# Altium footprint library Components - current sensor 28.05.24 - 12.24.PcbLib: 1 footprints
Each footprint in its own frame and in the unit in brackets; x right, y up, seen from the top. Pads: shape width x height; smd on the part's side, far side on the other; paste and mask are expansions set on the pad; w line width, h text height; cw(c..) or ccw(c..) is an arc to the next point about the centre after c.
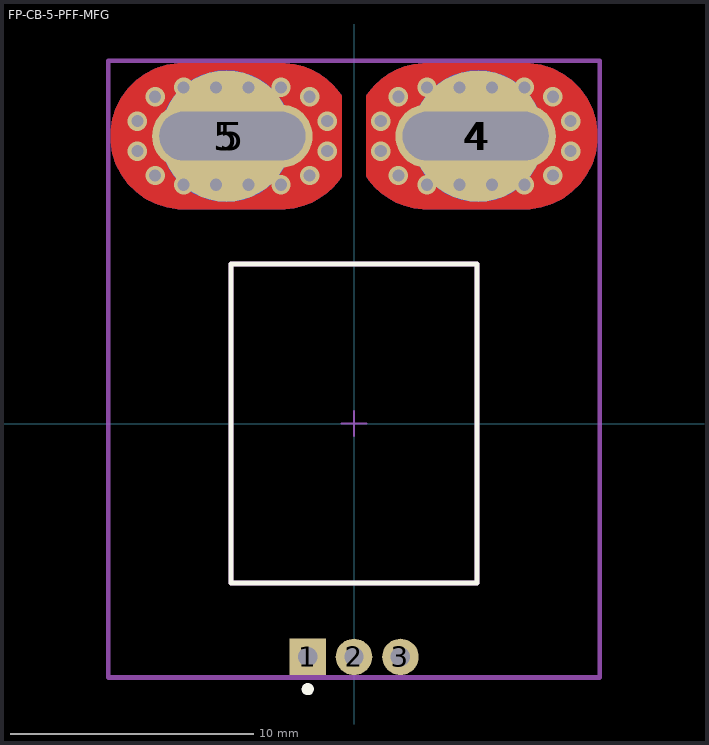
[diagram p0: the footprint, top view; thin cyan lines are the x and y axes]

## FP-CB-5-PFF-MFG [mm]
pads (9):
  rect 1.5x1.5 hole 0.8 paste-2539.97 mask+0: 1(-1.91,-9.59)
  round 1.5 hole 0.8 paste-2539.97 mask+0: 2(0,-9.59) 3(1.91,-9.59)
  rrect100% 6.6x2.6 hole 2 slot 6 at 0 deg paste-2539.97 mask+0: 4(5,11.809) 5(-5,11.809)
  round 5.4 smd paste-1000 mask+0: 4(5.099,11.809) 5(-5.25,11.809)
  round 5.4 smd far side paste-1000 mask+0: 4(5.099,11.809) 5(-5.25,11.809)
via 1.824,10.192 diameter 0.8 hole 0.5
via -1.824,10.192 diameter 0.8 hole 0.5
via 1.098,11.191 diameter 0.8 hole 0.5
via -1.098,11.191 diameter 0.8 hole 0.5
via 1.098,12.428 diameter 0.8 hole 0.5
via -1.098,12.428 diameter 0.8 hole 0.5
via 1.824,13.427 diameter 0.8 hole 0.5
via -1.824,13.427 diameter 0.8 hole 0.5
via 8.176,10.192 diameter 0.8 hole 0.5
via -8.176,10.192 diameter 0.8 hole 0.5
via 8.902,11.191 diameter 0.8 hole 0.5
via -8.902,11.191 diameter 0.8 hole 0.5
via 8.902,12.428 diameter 0.8 hole 0.5
via -8.902,12.428 diameter 0.8 hole 0.5
via 8.176,13.427 diameter 0.8 hole 0.5
via -8.176,13.427 diameter 0.8 hole 0.5
via 7,9.81 diameter 0.8 hole 0.5
via 5.667,9.81 diameter 0.8 hole 0.5
via 4.333,9.81 diameter 0.8 hole 0.5
via 3,9.81 diameter 0.8 hole 0.5
via 7,13.809 diameter 0.8 hole 0.5
via 5.667,13.809 diameter 0.8 hole 0.5
via 4.333,13.809 diameter 0.8 hole 0.5
via 3,13.809 diameter 0.8 hole 0.5
via -3,9.81 diameter 0.8 hole 0.5
via -4.333,9.81 diameter 0.8 hole 0.5
via -5.667,9.81 diameter 0.8 hole 0.5
via -7,9.81 diameter 0.8 hole 0.5
via -3,13.809 diameter 0.8 hole 0.5
via -4.333,13.809 diameter 0.8 hole 0.5
via -5.667,13.809 diameter 0.8 hole 0.5
via -7,13.809 diameter 0.8 hole 0.5
Top Layer:
  region: 0.5,13.468 0.602,13.622 0.843,13.903 1.116,14.152 1.418,14.365 1.744,14.54 2.089,14.674 2.448,14.764 2.815,14.809 3,14.809 7,14.809 7.236,14.809 7.703,14.736 8.152,14.59 8.572,14.375 8.954,14.098 9.288,13.764 9.566,13.382 9.78,12.961 9.926,12.512 10,12.046 10,11.573 9.926,11.107 9.78,10.658 9.566,10.237 9.288,9.855 8.954,9.521 8.572,9.244 8.152,9.029 7.703,8.883 7.236,8.809 7,8.809 3,8.809 2.815,8.809 2.448,8.855 2.089,8.945 1.744,9.079 1.418,9.254 1.116,9.467 0.843,9.716 0.602,9.997 0.5,10.151
  region: -0.5,10.151 -0.602,9.997 -0.843,9.716 -1.116,9.467 -1.418,9.254 -1.744,9.079 -2.089,8.945 -2.448,8.855 -2.815,8.81 -3,8.81 -7,8.809 -7.236,8.809 -7.703,8.883 -8.152,9.029 -8.572,9.244 -8.954,9.521 -9.288,9.855 -9.566,10.237 -9.78,10.658 -9.926,11.107 -10,11.573 -10,12.046 -9.926,12.512 -9.78,12.961 -9.566,13.382 -9.288,13.764 -8.954,14.098 -8.572,14.375 -8.152,14.59 -7.703,14.736 -7.236,14.809 -7,14.809 -7,14.81 -3,14.809 -2.815,14.809 -2.448,14.764 -2.089,14.674 -1.744,14.54 -1.418,14.365 -1.116,14.152 -0.843,13.903 -0.602,13.622 -0.5,13.468
Bottom Layer:
  region: 0.5,13.468 0.602,13.622 0.843,13.903 1.116,14.152 1.418,14.365 1.744,14.54 2.089,14.674 2.448,14.764 2.815,14.809 3,14.809 7,14.809 7.236,14.809 7.703,14.736 8.152,14.59 8.572,14.375 8.954,14.098 9.288,13.764 9.566,13.382 9.78,12.961 9.926,12.512 10,12.046 10,11.573 9.926,11.107 9.78,10.658 9.566,10.237 9.288,9.855 8.954,9.521 8.572,9.244 8.152,9.029 7.703,8.883 7.236,8.809 7,8.809 3,8.809 2.815,8.809 2.448,8.855 2.089,8.945 1.744,9.079 1.418,9.254 1.116,9.467 0.843,9.716 0.602,9.997 0.5,10.151
  region: -0.5,10.151 -0.602,9.997 -0.843,9.716 -1.116,9.467 -1.418,9.254 -1.744,9.079 -2.089,8.945 -2.448,8.855 -2.815,8.81 -3,8.81 -7,8.809 -7.236,8.809 -7.703,8.883 -8.152,9.029 -8.572,9.244 -8.954,9.521 -9.288,9.855 -9.566,10.237 -9.78,10.658 -9.926,11.107 -10,11.573 -10,12.046 -9.926,12.512 -9.78,12.961 -9.566,13.382 -9.288,13.764 -8.954,14.098 -8.572,14.375 -8.152,14.59 -7.703,14.736 -7.236,14.809 -7,14.809 -7,14.81 -3,14.809 -2.815,14.809 -2.448,14.764 -2.089,14.674 -1.744,14.54 -1.418,14.365 -1.116,14.152 -0.843,13.903 -0.602,13.622 -0.5,13.468
Top Overlay:
  circle w0.25: c-1.9,-10.916 r0.125
  lines w0.2: -5.05,-6.55 -5.05,6.55 5.05,6.55 5.05,-6.55 -5.05,-6.55
Top Assembly:
  lines w0.2: -10.099,-10.44 -10.099,14.91 10.099,14.91 10.099,-10.44 -10.099,-10.44
  text ".Designator" at 0,2.422 h1
Top 3D Body:
  lines w0.2: -5.05,-6.55 -5.05,6.55 5.05,6.55 5.05,-6.55 -5.05,-6.55
Top Courtyard:
  lines w0.2: -10.099,-10.44 -10.099,14.91 10.099,14.91 10.099,-10.44 -10.099,-10.44
Top Component Center:
  lines w0.1: -0.5,0 0.5,0 ; 0,-0.5 0,0.5
3D body "IC_Allegro_MicroSystems_LLC_ACS756KCB-050B-PFF-T_eec.STEP": height 0.25, standoff 0, extent -10.099,-10.44 10.099,14.91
